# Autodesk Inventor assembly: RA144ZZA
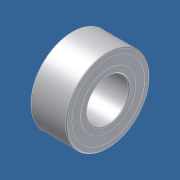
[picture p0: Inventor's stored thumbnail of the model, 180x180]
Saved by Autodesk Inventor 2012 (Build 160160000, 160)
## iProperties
Category: PARTsolutions
Created: 2011-07
Part Number: RA144ZZA
Catalog Web Link: www.cadenas.de
Description: With double shield ZZ -
Document SubType Name: Assembly
Designer: PARTsolutions
NB: RA144ZZA
NN: With double shield ZZ
NBSYN: RA144ZZA
LINA: RA144ZZA
PSOL_MULTISOLIDPART: 0.0
SD: 3.175
D: 6.350
B: 2.380
B1: 2.779
D1: 7.52
D2: 7.52
C1: 0.58
C2: 0.79
R: 0.08
ORDER: RA144ZZA
CR: 284
COR: 96
CRF: 29
CORF: 10
LSG: 59000
LSO: 70000
MASS: 0.27
ORDER1: R144
WSS: RA144ZA
WDS: RA144ZZA
UTWF: FLR144
FORSS: FLRA144ZA
FORDS: FLRA144ZZA
DA1: 3.9
DA2: 4
DA: 5.5
RAS: 0.08
MASS1: 0.33
VERS: 3
X: 1.587
N: 9
O: 14.954
RB: 0.470
PPATH: iss_asmtpl.prj
KT: DUMMY
CreationOption_UseAsmMates: 0
SUPPLIER: NTN
ARTICLENO: RA144ZZA
BOMINFO: RA144ZZA
CREATOR: CADENAS GmbH
PSOL_IDENT_0: {\\10.0.0.251\ps_data\23d-libs\ntn\ball_roller_bearings\miniature_extra_small_bb\inch_system_sizes\i
PSOL_IDENT_1: ss_zz_asmtab.prj},181 {VTYP=3D},{STYP=ASSTAB},{NB=RA144ZZA},{LINA=RA144ZZA},{NN=With double shield Z
PSOL_IDENT_2: Z},{DATE=11.12.2007 08:48:22},{GEOMDATE=02.04.2007},{VERSION=},{LINEID=16080},{LINESUBID=-1},{WBVAR=
PSOL_IDENT_3: }  {NB=RA144ZZA},{LINA=RA144ZZA},{KT=DUMMY},{IDNR=},{SD=3.175},{D=6.350},{B=2.380},{B1=2.779},{D1=7.
PSOL_IDENT_4: 52},{D2=7.52},{C1=0.58},{C2=0.79},{R=0.08},{ORDER=RA144ZZA},{CR=284},{COR=96},{CRF=29},{CORF=10},{LS
PSOL_IDENT_5: G=59000},{LSO=70000},{MASS=0.27},{ORDER1=R144},{WSS=RA144ZA},{WDS=RA144ZZA},{UTWF=FLR144},{FORSS=FLR
PSOL_IDENT_6: A144ZA},{FORDS=FLRA144ZZA},{DA1=3.9},{DA2=4},{DA=5.5},{RAS=0.08},{MASS1=0.33},{VERS=3},{X=1.5875},{N
PSOL_IDENT_7: =9},{O=14.95425},{RB=0.4699},{PPATH=iss_asmtpl.prj}
Title: RA144ZZA
Author: Cadenas PARTsolutions
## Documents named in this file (5)
- D:\Formulaire\Sujet CIM 2012\Modélisation_7970_shimano\éléments standards\PARTserver35516212\RA144ZZA.iam
- D:\Formulaire\Sujet CIM 2012\Modélisation_7970_shimano\éléments standards\PARTserver35516212\RA144ZZA_Inner_ring.ipt
- D:\Formulaire\Sujet CIM 2012\Modélisation_7970_shimano\éléments standards\PARTserver35516212\RA144ZZA_Outer_ring.ipt
- D:\Formulaire\Sujet CIM 2012\Modélisation_7970_shimano\éléments standards\PARTserver35516212\RA144ZZA_Shield.ipt
- D:\Formulaire\Sujet CIM 2012\Modélisation_7970_shimano\éléments standards\PARTserver35516212\RA144ZZA_Ball.ipt
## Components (13 placed, 4 different names)
1. RA144ZZA Inner ring:1
2. RA144ZZA Outer ring:1
3. RA144ZZA Shield:1
4. RA144ZZA Shield:2
5. RA144ZZA Ball:1
6. RA144ZZA Ball:2
7. RA144ZZA Ball:3
8. RA144ZZA Ball:4
9. RA144ZZA Ball:5
10. RA144ZZA Ball:6
11. RA144ZZA Ball:7
12. RA144ZZA Ball:8
13. RA144ZZA Ball:9
